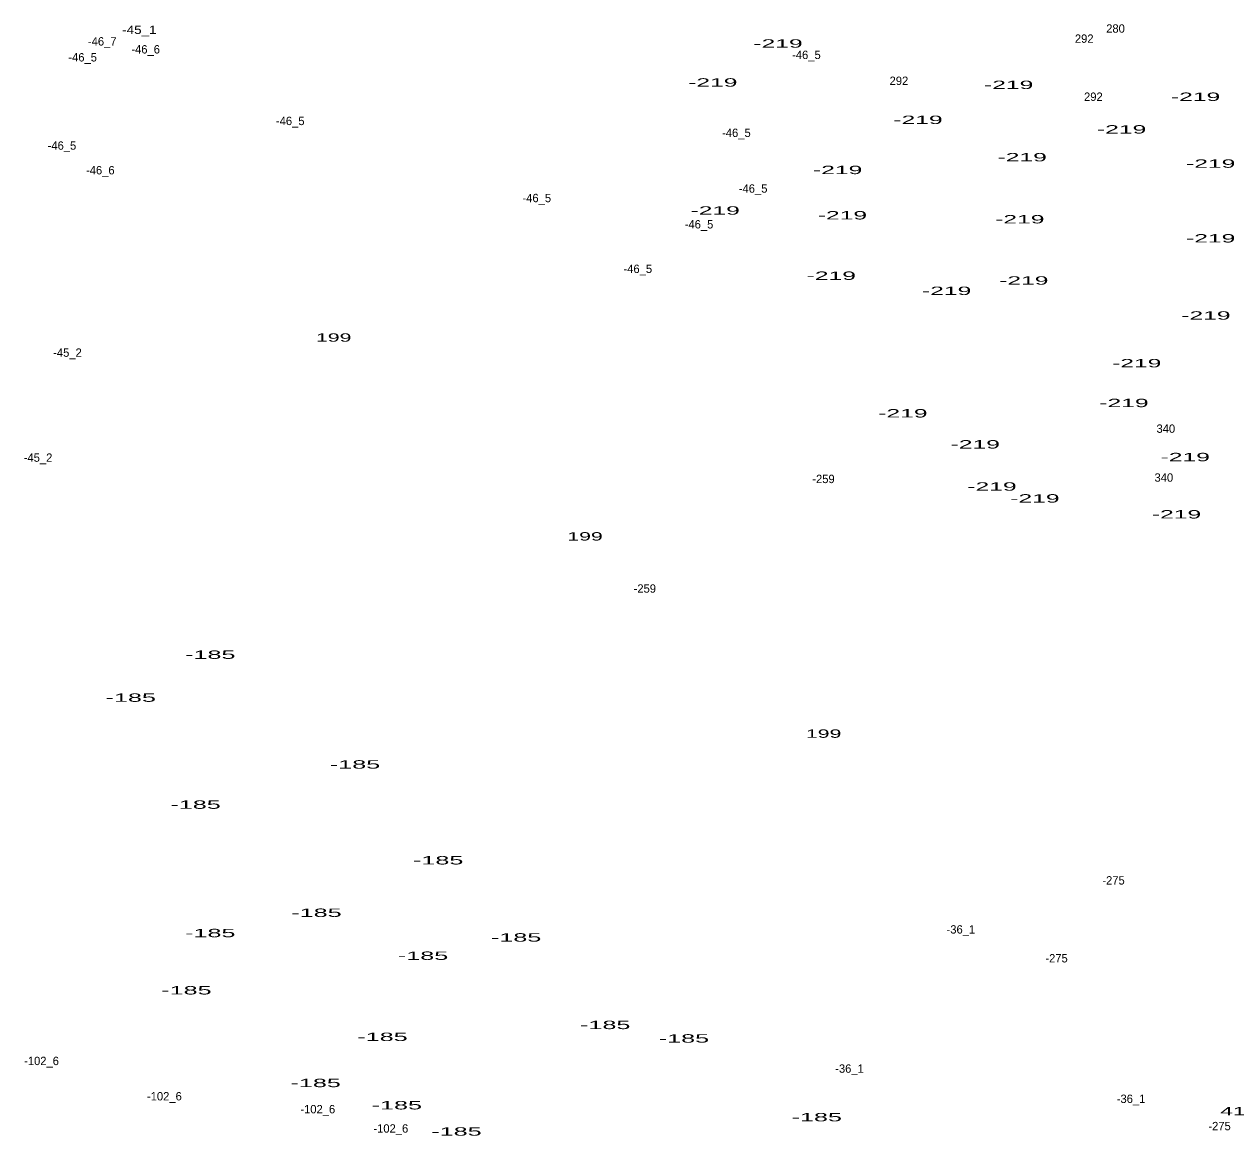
# Model space of a CAD drawing. Extents: x -658595 to -655205, y -1004347 to -1000147.
# Drawn here: x -657459 to -656879, y -1001196 to -1000664 of the extents above; entities that cross this region are included whole.
import ezdxf
from ezdxf.enums import TextEntityAlignment as Align

# ---------------------------------------------------------------- set-up
doc = ezdxf.new("R2010")
doc.units = 0
doc.header["$LTSCALE"] = 1.6
doc.layers.add('24', color=7, linetype='Continuous')

msp = doc.modelspace()

# ---------------------------------------------------------------- texts
at = {"layer": '24'}
for s, width, p in [('-45_1', 1.2, (-657403.689, -1000668.68)), ('-219', 2.2, (-657098.275, -1000675.22)), ('-219', 2.2, (-657129.465, -1000693.87)), ('-219', 2.2, (-656987.975, -1000695.01)), ('-219', 2.2, (-656898.585, -1000700.71)), ('-219', 2.2, (-657031.335, -1000711.75)), ('-219', 2.2, (-656933.955, -1000716.31)), ('-219', 2.2, (-656981.505, -1000729.63)), ('-219', 2.2, (-656891.355, -1000732.68)), ('-219', 2.2, (-657069.745, -1000735.72)), ('-219', 2.2, (-657128.325, -1000755.12)), ('-219', 2.2, (-657067.465, -1000757.41)), ('-219', 2.2, (-656982.645, -1000759.31)), ('-219', 2.2, (-656891.355, -1000768.44)), ('-219', 2.2, (-657072.795, -1000786.33)), ('-219', 2.2, (-656980.745, -1000788.61)), ('-219', 2.2, (-657017.635, -1000793.56)), ('-219', 2.2, (-656893.645, -1000805.35)), ('199', 1.9, (-657310.767, -1000815.91)), ('-219', 2.2, (-656926.735, -1000828.18)), ('-219', 2.2, (-656932.815, -1000847.21)), ('-219', 2.2, (-657038.555, -1000852.16)), ('-219', 2.2, (-657003.945, -1000867)), ('-219', 2.2, (-656903.525, -1000873.09)), ('-219', 2.2, (-656995.955, -1000887.17)), ('-219', 2.2, (-656975.415, -1000892.87)), ('-219', 2.2, (-656907.705, -1000900.48)), ('199', 1.9, (-657190.567, -1000911.03)), ('-185', 2.25, (-657369.781, -1000967.64)), ('-185', 2.25, (-657407.811, -1000988.19)), ('199', 1.9, (-657076.457, -1001005.4)), ('-185', 2.25, (-657300.551, -1001020.15)), ('-185', 2.25, (-657376.811, -1001039.38)), ('-185', 2.25, (-657260.791, -1001066.01)), ('-185', 2.25, (-657318.991, -1001091.12)), ('-185', 2.25, (-657369.781, -1001100.82)), ('-185', 2.25, (-657223.511, -1001102.92)), ('-185', 2.25, (-657268.021, -1001111.67)), ('-185', 2.25, (-657381.191, -1001128.21)), ('-185', 2.25, (-657180.911, -1001144.77)), ('-185', 2.25, (-657287.421, -1001150.48)), ('-185', 2.25, (-657143.261, -1001151.24)), ('-185', 2.25, (-657319.371, -1001172.55)), ('-185', 2.25, (-657280.571, -1001183.2)), ('413', 2.05, (-656877.663, -1001186.05)), ('-185', 2.25, (-657079.741, -1001188.91)), ('-185', 2.25, (-657252.041, -1001195.76))]:
    msp.add_text(s, height=4, dxfattribs=dict(at, width=width)).set_placement(p, align=Align.CENTER)
for s, p in [('280', (-656936.871, -1000668.07)), ('-46_7', (-657421.448, -1000674.22)), ('292', (-656951.833, -1000672.9)), ('-46_5', (-657430.822, -1000681.83)), ('-46_6', (-657400.688, -1000678.02)), ('-46_5', (-657084.692, -1000680.67)), ('292', (-657040.453, -1000693.07)), ('292', (-656947.463, -1000700.68)), ('-46_5', (-657331.542, -1000712.27)), ('-46_5', (-657118.172, -1000717.96)), ('-46_5', (-657440.712, -1000724.06)), ('-46_6', (-657422.368, -1000735.86)), ('-46_5', (-657110.172, -1000744.61)), ('-46_5', (-657213.632, -1000749.17)), ('-46_5', (-657136.042, -1000761.73)), ('-46_5', (-657165.322, -1000783.04)), ('-45_2', (-657438.067, -1000823.12)), ('340', (-656912.815, -1000859.49)), ('-45_2', (-657452.147, -1000873.35)), ('-259', (-657076.53, -1000883.55)), ('340', (-656913.765, -1000882.89)), ('-259', (-657161.97, -1000935.99)), ('-275', (-656937.821, -1001075.62)), ('-36_1', (-657010.832, -1001099.08)), ('-275', (-656965.081, -1001112.88)), ('-102_6', (-657450.476, -1001162)), ('-36_1', (-657064.082, -1001165.66)), ('-102_6', (-657391.726, -1001178.9)), ('-36_1', (-656929.432, -1001180.12)), ('-102_6', (-657318.376, -1001185.09)), ('-102_6', (-657283.436, -1001194.31)), ('-275', (-656887.121, -1001193.18))]:
    msp.add_text(s, height=4, dxfattribs=at).set_placement(p, align=Align.CENTER)

doc.saveas('drawing.dxf')
